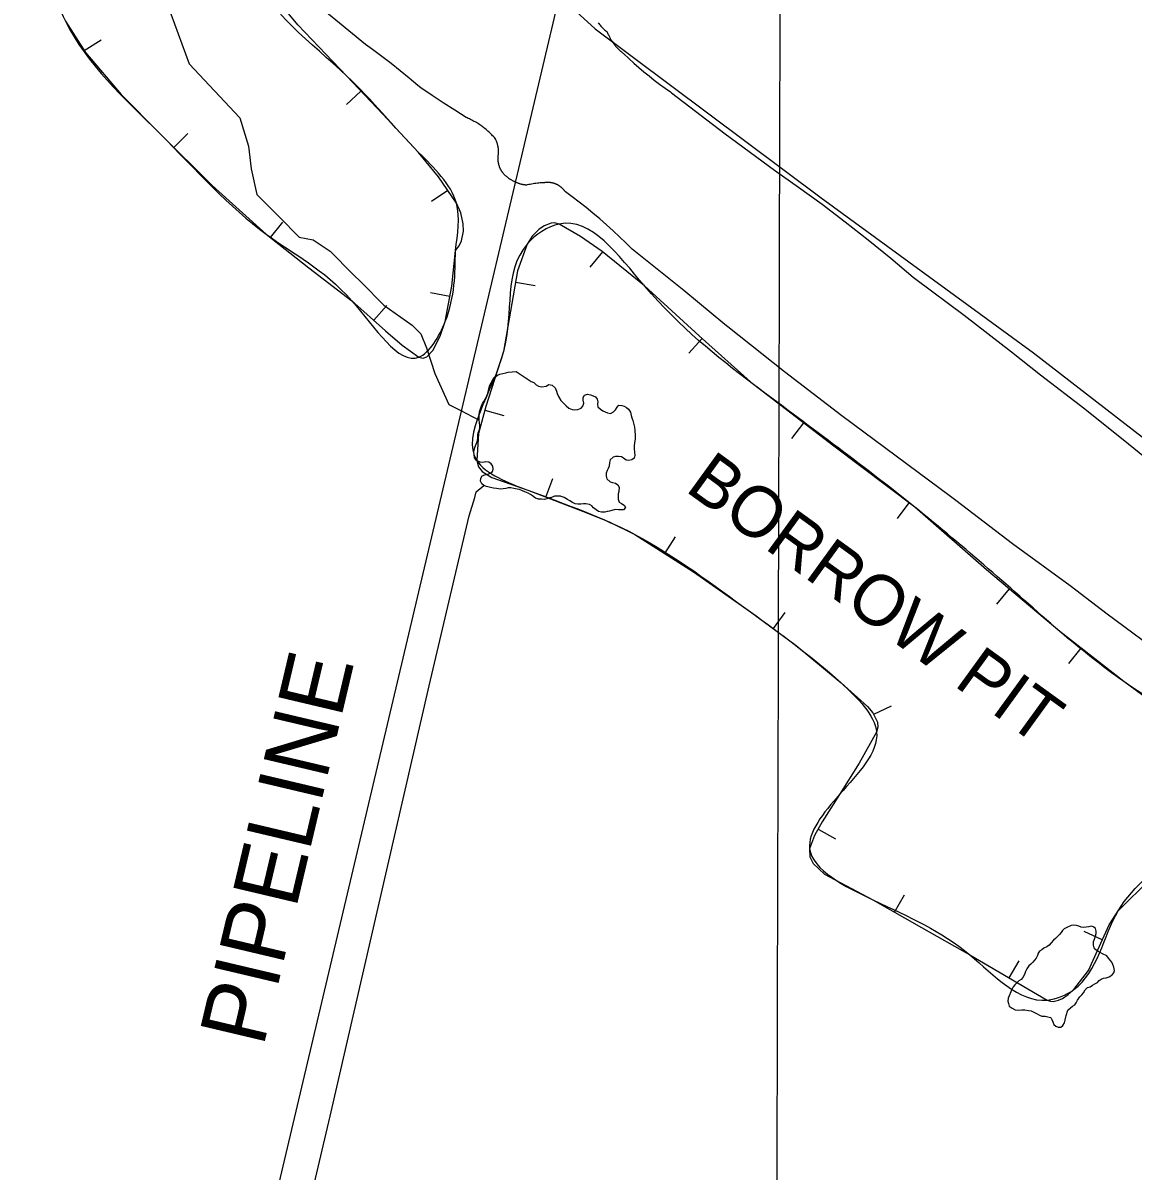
# Model space of a CAD drawing. Extents: x 3172297 to 3210190, y 958463 to 983887.
# Drawn here: x 3186026 to 3187425, y 966663 to 968110 of the extents above; entities that cross this region are included whole.
import ezdxf

# ---------------------------------------------------------------- set-up
doc = ezdxf.new("R2010")
doc.units = 0
for name, color, linetype in [('V-BORW-LINE', 7, 'Continuous'), ('V-GRID-MAJR', 7, 'Continuous'), ('V-LEVE-TOET', 7, 'Continuous'), ('V-RIVR-RANG', 7, 'Continuous'), ('V-TOPO-SHOR', 7, 'Continuous'), ('V-UTIL-IDEN', 7, 'Continuous'), ('V-UTIL-LINE', 7, 'Continuous')]:
    doc.layers.add(name, color=color, linetype=linetype)

msp = doc.modelspace()

# ---------------------------------------------------------------- linework, layer by layer
at = {"layer": 'V-BORW-LINE'}
for p, q in [((3186103.2, 968075), (3186124.3, 968088.5)), ((3186451.8, 968024.1), (3186433.6, 968007)), ((3186216.2, 967952.8), (3186233.8, 967970.5)), ((3186561.3, 967898.9), (3186540.6, 967884.8)), ((3186338, 967839.3), (3186353.5, 967858.9)), ((3186756.2, 967821.6), (3186740.5, 967802.2)), ((3186646.6, 967783.3), (3186671.3, 967779.1)), ((3186564, 967765), (3186539.5, 967769.6)), ((3186468, 967735.2), (3186484.6, 967753.9)), ((3186881.9, 967712.3), (3186865.2, 967693.6)), ((3186608, 967621.7), (3186632.1, 967615.1)), ((3187009.8, 967605.8), (3186994.6, 967586)), ((3186684.7, 967512.3), (3186693.7, 967535.7)), ((3187142.6, 967505.1), (3187127.6, 967485.2)), ((3186834.8, 967441.3), (3186848.2, 967462.4)), ((3187269, 967396.6), (3187252.9, 967377.5)), ((3186971.7, 967346.5), (3186986.5, 967366.7)), ((3187359, 967322.1), (3187343.6, 967302.5)), ((3187098.1, 967238.6), (3187120.6, 967249.4)), ((3187028, 967093.8), (3187049.8, 967081.5)), ((3187124.5, 966989.2), (3187136.8, 967011)), ((3187386.2, 966954.5), (3187363.4, 966964.7)), ((3187268.9, 966906.3), (3187281.5, 966927.9))]:
    msp.add_line(p, q, dxfattribs=at)
for points in [[(3186570.9, 967823), (3186575.6, 967829.1), (3186578.5, 967835.3), (3186581, 967847.3), (3186580.8, 967856.8), (3186577.8, 967870.7), (3186572.1, 967882.8), (3186549.8, 967915.8), (3186524.6, 967946.8), (3186479.3, 967994.9), (3186434, 968043), (3186372.5, 968107.6), (3186313.9, 968178.4)], [(3186079.4, 968112.2), (3186104.8, 968072.6), (3186149.7, 968019.6), (3186198.8, 967970), (3186264.2, 967905.1), (3186332.5, 967843.6), (3186386.3, 967801.4), (3186440.4, 967759.7), (3186483, 967721.9)], [(3187332.6, 967342.9), (3187240.5, 967420.7), (3187150, 967499.6), (3187047.9, 967576.4), (3186946.6, 967654.4), (3186878.1, 967715.6), (3186809.3, 967778.5), (3186756, 967821.8), (3186728.7, 967840.8), (3186701.6, 967856.5), (3186696.4, 967857.9), (3186691.6, 967857.6), (3186682.7, 967854.1), (3186676.2, 967849.7), (3186667.6, 967841), (3186661.3, 967831.1), (3186649, 967797.3), (3186631.5, 967695.8), (3186609.4, 967626.7), (3186600.1, 967592.4), (3186597.8, 967558.5), (3186600.2, 967550.4), (3186604.8, 967544.6), (3186616.9, 967536.9), (3186663.3, 967520.6), (3186731.1, 967494.4), (3186764.7, 967481.2), (3186797.1, 967465.2), (3186871.1, 967418.3), (3186942.7, 967367.7), (3187000.5, 967325.4), (3187057, 967278.2), (3187090.5, 967248.5), (3187097.1, 967240.6), (3187102.9, 967228.5), (3187103.3, 967222.4), (3187101.7, 967216.2), (3187079.7, 967176.9), (3187055, 967137.4), (3187033.3, 967103.2), (3187023.7, 967086), (3187017.4, 967069.2), (3187017.6, 967058.8), (3187021.9, 967050.4), (3187036.3, 967037.2), (3187097, 967004.8), (3187158.3, 966969.9), (3187219.5, 966935.2), (3187268.2, 966906.7), (3187316.9, 966878.4), (3187320.9, 966876.9), (3187324.5, 966876.7), (3187331.1, 966878.1), (3187336.1, 966880.5), (3187343.4, 966885.5), (3187350.2, 966891.5), (3187368.8, 966915.7), (3187386.3, 966954.6), (3187394.9, 966973.4), (3187406.1, 966990.7), (3187446.9, 967031.3)], [(3186483, 967721.9), (3186504, 967703.6), (3186525, 967688.7), (3186530.3, 967687.5), (3186534.8, 967689.2), (3186542.3, 967697), (3186551.9, 967715.2), (3186558.2, 967733.8), (3186566.5, 967778.3), (3186570.9, 967823)], [(3187457.9, 967247.2), (3187413.5, 967279.7), (3187373, 967311.2), (3187332.6, 967342.9)]]:
    msp.add_lwpolyline(points, dxfattribs=at)
for points in [[(3186570.9, 967823), (3186558.2, 967733.8), (3186525, 967688.7), (3186440.4, 967759.7), (3186332.5, 967843.6), (3186198.8, 967970), (3186079.4, 968112.2), (3186046.2, 968212.5), (3186028.1, 968294.9), (3186058.5, 968423.3), (3186144.3, 968634.5), (3186233.5, 968911.2), (3186317.2, 969158.1), (3186384.1, 969385.4), (3186404.4, 969615.9), (3186453, 969857.5), (3186463.9, 970055.1), (3186468.3, 970206), (3186442.7, 970412), (3186424.7, 970627), (3186444.1, 970707.7), (3186526.6, 970731.5), (3186576.5, 970720.7), (3186595.8, 970686.3), (3186618.9, 970575.1), (3186622.1, 970412), (3186626.9, 970258.7), (3186635, 970085.5), (3186634.7, 969845.8), (3186644.2, 969674.8), (3186610.1, 969512.4), (3186553.6, 969289.4), (3186481.5, 969027.9), (3186445.6, 968873.5), (3186394.3, 968683.3), (3186345.5, 968468), (3186307, 968292), (3186313.9, 968178.4), (3186434, 968043), (3186524.6, 967946.8), (3186572.1, 967882.8), (3186570.9, 967823)], [(3187332.6, 967342.9), (3187413.5, 967279.7), (3187502.6, 967213), (3187533, 967163.3), (3187488.5, 967075), (3187406.1, 966990.7), (3187350.2, 966891.5), (3187316.9, 966878.4), (3187219.5, 966935.2), (3187097, 967004.8), (3187017.4, 967069.2), (3187055, 967137.4), (3187101.7, 967216.2), (3187057, 967278.2), (3186942.7, 967367.7), (3186797.1, 967465.2), (3186663.3, 967520.6), (3186597.8, 967558.5), (3186631.5, 967695.8), (3186661.3, 967831.1), (3186701.6, 967856.5), (3186809.3, 967778.5), (3186946.6, 967654.4), (3187150, 967499.6), (3187332.6, 967342.9)]]:
    msp.add_spline(points, degree=3, dxfattribs=at)
at = {"layer": 'V-GRID-MAJR'}
msp.add_spline([(3186968.9, 963893.7), (3186984.8, 969954), (3187000.7, 976017.3), (3187016.6, 982080.8), (3187016.6, 982083.8)], degree=3, dxfattribs=at)
at = {"layer": 'V-LEVE-TOET'}
for points in [[(3186621.8, 967962.7), (3186621.6, 967963.2), (3186621.3, 967963.8), (3186621.1, 967964.1), (3186621.1, 967964.1), (3186620, 967965.4), (3186619, 967966.6), (3186617.8, 967967.8), (3186616.7, 967969), (3186615.5, 967970.2), (3186614.4, 967971.3), (3186613.2, 967972.5), (3186612, 967973.6), (3186610.7, 967974.7), (3186609.5, 967975.7), (3186608.2, 967976.8), (3186606.9, 967977.8), (3186605.6, 967978.8), (3186604.3, 967979.8), (3186602.9, 967980.7), (3186601.6, 967981.7), (3186600.2, 967982.6), (3186598.8, 967983.4), (3186597.4, 967984.3), (3186596, 967985.1), (3186594.5, 967985.9), (3186593.1, 967986.7), (3186591.6, 967987.5), (3186590.1, 967988.2), (3186588.6, 967988.9), (3186587.1, 967989.6), (3186585.6, 967990.3), (3186584.6, 967990.7), (3186584.6, 967990.7), (3186570.1, 967999.8), (3186555.7, 968009.1), (3186541.5, 968018.6), (3186527.4, 968028.3), (3186523.7, 968030.9), (3186523.7, 968030.9), (3186512.6, 968040.4), (3186501.3, 968049.7), (3186489.9, 968058.8), (3186478.3, 968067.7), (3186466.6, 968076.4), (3186457.8, 968082.7), (3186457.8, 968082.7), (3186382.7, 968144.6)], [(3186750.9, 968110.1), (3186751.7, 968109.1), (3186752.6, 968108), (3186753.4, 968107), (3186754.3, 968106), (3186755.2, 968105.1), (3186756.1, 968104.1), (3186757.1, 968103.1), (3186758, 968102.2), (3186759, 968101.3), (3186760, 968100.4), (3186761, 968099.5), (3186762, 968098.7), (3186762.4, 968098.3), (3186762.4, 968098.3), (3186762.8, 968097.3), (3186763.2, 968096.3), (3186763.6, 968095.3), (3186764.1, 968094.3), (3186764.6, 968093.4), (3186765.1, 968092.4), (3186765.6, 968091.4), (3186766.1, 968090.5), (3186766.6, 968089.6), (3186767.2, 968088.6), (3186767.8, 968087.7), (3186768.4, 968086.8), (3186769, 968085.9), (3186769.6, 968085), (3186770.2, 968084.1), (3186770.9, 968083.2), (3186771.5, 968082.4), (3186772.2, 968081.5), (3186772.9, 968080.7), (3186773.6, 968079.9), (3186774.3, 968079.1), (3186775.1, 968078.3), (3186775.8, 968077.5)], [(3186775.8, 968077.5), (3186776.6, 968076.7), (3186777.4, 968076), (3186778.2, 968075.2), (3186779, 968074.5), (3186779.8, 968073.8), (3186780.6, 968073.1), (3186781.5, 968072.4), (3186782.3, 968071.7), (3186783.2, 968071.1), (3186783.4, 968070.9), (3186783.4, 968070.9), (3186789.5, 968065.1), (3186795.8, 968059.4), (3186802.1, 968053.9), (3186808.5, 968048.4), (3186815, 968043.1), (3186821.6, 968037.8), (3186828.3, 968032.7), (3186835.1, 968027.7), (3186841.9, 968022.9), (3186843.3, 968021.9), (3186843.3, 968021.9), (3186910.9, 967970.2), (3186973.2, 967924.2), (3186973.2, 967924.2), (3187003.3, 967903.1), (3187033, 967881.4), (3187062.3, 967859.2), (3187091.2, 967836.6), (3187119.7, 967813.4), (3187147.8, 967789.7), (3187151.2, 967786.8), (3187151.2, 967786.8), (3187212, 967741.6), (3187272, 967695.3), (3187308.2, 967666.5), (3187308.2, 967666.5), (3187364.2, 967623.5), (3187419.3, 967579.6), (3187461.5, 967545.1)], [(3186641.3, 967912), (3186640.6, 967912.4), (3186640, 967912.8), (3186639.4, 967913.2), (3186638.8, 967913.6), (3186638.2, 967914), (3186637.6, 967914.5), (3186637, 967914.9), (3186636.4, 967915.4), (3186635.8, 967915.9), (3186635.2, 967916.3), (3186634.7, 967916.8), (3186634.1, 967917.3), (3186633.6, 967917.8), (3186633, 967918.4), (3186632.5, 967918.9), (3186632, 967919.4), (3186631.5, 967920), (3186631, 967920.5), (3186630.7, 967920.9), (3186630.7, 967920.9), (3186630.4, 967921.3), (3186630.1, 967921.8), (3186629.8, 967922.2), (3186629.5, 967922.7), (3186629.2, 967923.1), (3186628.9, 967923.6), (3186628.7, 967924), (3186628.4, 967924.5), (3186628.2, 967925), (3186627.9, 967925.4), (3186627.7, 967925.9), (3186627.5, 967926.4), (3186627.3, 967926.9), (3186627, 967927.4), (3186626.8, 967927.9), (3186626.7, 967928.3), (3186626.5, 967928.8), (3186626.3, 967929.3), (3186626.1, 967929.8), (3186626, 967930.3), (3186625.8, 967930.9), (3186625.7, 967931.4), (3186625.6, 967931.9), (3186625.5, 967932.4), (3186625.3, 967932.9), (3186625.2, 967933.4), (3186625.1, 967933.9), (3186625.1, 967934.5), (3186625, 967935), (3186624.9, 967935.5), (3186624.9, 967936), (3186624.8, 967936.6), (3186624.8, 967937.1), (3186624.8, 967937.6), (3186624.7, 967938.1), (3186624.7, 967938.7), (3186624.7, 967939.2), (3186624.7, 967939.7), (3186624.7, 967940.2), (3186624.8, 967940.8), (3186624.8, 967941.3), (3186624.9, 967941.8), (3186624.9, 967942.3), (3186625, 967942.8), (3186625, 967943.4), (3186625.1, 967943.9), (3186625.2, 967944.4), (3186625.3, 967944.8), (3186625.3, 967944.8), (3186625.3, 967945.4), (3186625.4, 967946), (3186625.4, 967946.6), (3186625.4, 967947.2), (3186625.4, 967947.8), (3186625.4, 967948.4), (3186625.3, 967949), (3186625.3, 967949.5), (3186625.2, 967950.1), (3186625.2, 967950.7), (3186625.1, 967951.3), (3186625.1, 967951.9), (3186625, 967952.5), (3186624.9, 967953.1), (3186624.8, 967953.7), (3186624.7, 967954.3), (3186624.5, 967954.8), (3186624.4, 967955.4), (3186624.3, 967956), (3186624.1, 967956.6), (3186623.9, 967957.1), (3186623.8, 967957.7), (3186623.6, 967958.3), (3186623.4, 967958.8), (3186623.2, 967959.4), (3186623, 967960), (3186622.8, 967960.5), (3186622.6, 967961.1), (3186622.3, 967961.6), (3186622.1, 967962.2), (3186621.8, 967962.7)], [(3186705.6, 967901.6), (3186705.2, 967901.9), (3186704.9, 967902.2), (3186704.5, 967902.5), (3186704.2, 967902.8), (3186703.8, 967903.1), (3186703.4, 967903.4), (3186703, 967903.7), (3186702.7, 967904), (3186702.3, 967904.2), (3186701.9, 967904.5), (3186701.5, 967904.7), (3186701.1, 967905), (3186700.7, 967905.2), (3186700.3, 967905.5), (3186699.9, 967905.7), (3186699.5, 967905.9), (3186699.1, 967906.1), (3186698.6, 967906.3), (3186698.2, 967906.5), (3186697.8, 967906.7), (3186697.4, 967906.9), (3186696.9, 967907), (3186696.5, 967907.2), (3186696.1, 967907.4), (3186695.6, 967907.5), (3186695.2, 967907.7), (3186694.7, 967907.8), (3186694.3, 967907.9), (3186693.8, 967908.1), (3186693.4, 967908.2), (3186692.9, 967908.3), (3186692.5, 967908.4), (3186692, 967908.5), (3186691.6, 967908.5), (3186691.1, 967908.6), (3186690.6, 967908.7), (3186690.2, 967908.7), (3186689.7, 967908.8), (3186689.3, 967908.8), (3186688.8, 967908.8), (3186688.3, 967908.9), (3186687.9, 967908.9), (3186687.4, 967908.9), (3186686.9, 967908.9), (3186686.5, 967908.9), (3186686, 967908.9), (3186685.6, 967908.9), (3186685.1, 967908.8), (3186684.6, 967908.8), (3186684.2, 967908.7), (3186683.7, 967908.7), (3186683.3, 967908.6), (3186683.3, 967908.6), (3186681.5, 967908.5), (3186679.6, 967908.4), (3186677.8, 967908.3), (3186676, 967908.1), (3186674.2, 967907.9), (3186672.4, 967907.7), (3186670.6, 967907.4), (3186668.8, 967907.2), (3186667, 967906.8), (3186665.1, 967906.5), (3186663.3, 967906.1), (3186661.5, 967905.7), (3186660.6, 967905.5), (3186660.6, 967905.5), (3186660, 967905.6), (3186659.4, 967905.6), (3186658.8, 967905.7), (3186658.2, 967905.8), (3186657.6, 967905.8), (3186657, 967905.9), (3186656.4, 967906), (3186655.8, 967906.2), (3186655.2, 967906.3), (3186654.6, 967906.4), (3186654, 967906.6), (3186653.4, 967906.7), (3186652.8, 967906.9), (3186652.2, 967907.1), (3186651.7, 967907.3), (3186651.1, 967907.5), (3186650.5, 967907.7), (3186649.9, 967907.9), (3186649.4, 967908.1), (3186648.8, 967908.3), (3186648.2, 967908.6), (3186647.7, 967908.8), (3186647.3, 967909), (3186647.3, 967909), (3186646.6, 967909.3), (3186645.9, 967909.6), (3186645.2, 967909.9), (3186644.6, 967910.2), (3186643.9, 967910.6), (3186643.2, 967910.9), (3186642.6, 967911.2), (3186641.9, 967911.6), (3186641.3, 967912)], [(3187468.3, 967308.6), (3187392.2, 967364.9), (3187345.8, 967400.3), (3187345.8, 967400.3), (3187273.2, 967453.5), (3187201.6, 967508), (3187195, 967513.1), (3187195, 967513.1), (3187058, 967614.7), (3187058, 967614.7), (3186985.6, 967670.2), (3186914.1, 967726.9), (3186910.4, 967729.9), (3186910.4, 967729.9), (3186858.7, 967772.8), (3186806.4, 967814.7), (3186793.6, 967824.7), (3186793.6, 967824.7), (3186785.8, 967832.7), (3186777.7, 967840.4), (3186769.6, 967848.1), (3186761.3, 967855.6), (3186752.9, 967862.9), (3186744.3, 967870.1), (3186735.7, 967877.2), (3186726.9, 967884.1), (3186718, 967890.8), (3186709.5, 967897), (3186709.5, 967897), (3186709.2, 967897.4), (3186709, 967897.8), (3186708.7, 967898.2), (3186708.4, 967898.5), (3186708.1, 967898.9), (3186707.8, 967899.2), (3186707.5, 967899.6), (3186707.2, 967900), (3186706.9, 967900.3), (3186706.6, 967900.6), (3186706.2, 967901), (3186705.9, 967901.3), (3186705.6, 967901.6)]]:
    msp.add_lwpolyline(points, dxfattribs=at)
at = {"layer": 'V-TOPO-SHOR'}
for points in [[(3186924.2, 969734), (3186888, 969546.6), (3186819.5, 969291.4), (3186695, 968763.2), (3186594, 968374.2), (3186583.2, 968326.1), (3186581.4, 968302.9), (3186588.4, 968277.8), (3186599.1, 968254.6), (3186620.4, 968217.1), (3186700.6, 968145.4), (3186746.9, 968102.5), (3187032.1, 967889.3), (3187299.4, 967694), (3187871.5, 967251.6), (3187882.2, 967233.7), (3187869.6, 967214.1), (3187830.2, 967174.9)], [(3186198.3, 968159.8), (3186235.3, 968058.2), (3186299.4, 967990.2), (3186310, 967954.5), (3186313.5, 967925.9), (3186320.6, 967893.7), (3186349.1, 967865.1), (3186374, 967840), (3186391.8, 967836.4), (3186413.2, 967822.1), (3186441.7, 967793.4), (3186452.4, 967782.7), (3186480.9, 967754.1), (3186516.6, 967729), (3186527.3, 967718.2), (3186534.3, 967700.4), (3186545, 967668.2), (3186562.7, 967628.9), (3186577, 967621.7), (3186600.8, 967609.4)], [(3186627.1, 967667.3), (3186630.7, 967667.9), (3186634.4, 967668.9), (3186637.4, 967669.9), (3186647.7, 967670.6)], [(3186647.7, 967670.6), (3186666.4, 967658.1), (3186669.7, 967656.6), (3186672.8, 967654), (3186675.7, 967652.3), (3186679.7, 967651.2), (3186685.3, 967652.2), (3186688.5, 967654.3), (3186692.9, 967653.2), (3186696.6, 967650.2), (3186698.2, 967646), (3186699.3, 967643), (3186700.7, 967639.1), (3186703.8, 967634.2), (3186706.9, 967631), (3186710.4, 967627.2), (3186713.9, 967624.3), (3186717.9, 967622.8), (3186721, 967622.3), (3186725.4, 967622.7), (3186729.6, 967624.3), (3186731.7, 967627), (3186732.6, 967630.7), (3186732, 967634.5), (3186732, 967637.7), (3186733.8, 967640.6), (3186737.5, 967642), (3186741.1, 967641.3), (3186744.6, 967640), (3186747.5, 967638.5), (3186749.8, 967635.8), (3186750.6, 967632.4), (3186750.2, 967629.3), (3186750.5, 967626.2), (3186753.6, 967623.2), (3186756.8, 967621.1), (3186759.5, 967619.6), (3186762.6, 967618.5), (3186766.6, 967617.6), (3186770.3, 967619.9), (3186772.9, 967622.3), (3186774.6, 967625.7), (3186777.1, 967628.2), (3186780.7, 967627.7), (3186783.8, 967626.8), (3186786.7, 967625.1), (3186789, 967623), (3186791.5, 967619.2), (3186792.5, 967615.2), (3186793.1, 967612.1), (3186794.7, 967608.7), (3186796.7, 967600.3), (3186797.1, 967596.1), (3186797.6, 967589.8), (3186797.4, 967585.2), (3186796.7, 967580.9), (3186796.2, 967576.9), (3186796.4, 967573.1), (3186796.8, 967569.1), (3186796.9, 967564.7), (3186796.1, 967561.4), (3186793.3, 967559.3), (3186789.5, 967558.6), (3186786.2, 967558.8), (3186782.7, 967561.4), (3186780.2, 967563.1), (3186776.6, 967563.5), (3186772.6, 967563.6), (3186769.7, 967562.5), (3186766.1, 967559.2), (3186765.2, 967556.1), (3186764.6, 967551.3), (3186763.5, 967548.4), (3186762, 967545.7), (3186761.1, 967542.3), (3186760.9, 967538.8), (3186761.7, 967535.2), (3186766, 967531.6), (3186769.1, 967530.5), (3186772.9, 967529.9), (3186775.6, 967527.7), (3186777.2, 967525), (3186777, 967519.4), (3186775.9, 967516.4), (3186775.9, 967513.1), (3186776.2, 967509.7), (3186777.4, 967506), (3186780.4, 967504.3), (3186783.5, 967502.1), (3186785.3, 967499), (3186782.8, 967496.3)], [(3186782.8, 967496.3), (3186779.6, 967496.1), (3186776.5, 967496.1), (3186772.1, 967496.6), (3186768.1, 967495.6), (3186765.2, 967494.6), (3186762, 967494.2), (3186759.1, 967493.2), (3186755.1, 967493.2), (3186751.2, 967494.3), (3186748.3, 967496.3), (3186744.9, 967498.8), (3186742.7, 967501.1), (3186740, 967502.8), (3186735.4, 967503.7), (3186732.2, 967503.8), (3186728.9, 967503.4), (3186725.3, 967503.2), (3186721.8, 967503.7), (3186718.6, 967505.4), (3186715.3, 967507.5), (3186712.2, 967509.2), (3186707.8, 967511.6), (3186704.1, 967513.1), (3186703.3, 967513.5), (3186699.1, 967513.5), (3186695.7, 967513.4), (3186691.3, 967511.5), (3186690, 967511.3), (3186686.3, 967510.1), (3186683.3, 967509.3), (3186679.4, 967509.8), (3186675.2, 967509.8), (3186674.8, 967510.3), (3186671.8, 967511.1), (3186667.9, 967513.7), (3186665.4, 967515.6), (3186662.5, 967517.1), (3186658.3, 967519), (3186655.4, 967520.3), (3186651.9, 967522), (3186648.7, 967522.5), (3186644.6, 967523.1), (3186640.8, 967523.8), (3186637.5, 967524.1), (3186634.3, 967523.3), (3186631.2, 967522.7), (3186627.8, 967522.3), (3186622.8, 967523.2), (3186619, 967523.4), (3186615.1, 967524.3), (3186610.3, 967525.6), (3186606.7, 967526.9), (3186604.3, 967529.2), (3186602.6, 967532.2), (3186602.9, 967536.2), (3186604.6, 967539.1), (3186608.1, 967540.5), (3186611.7, 967541.3), (3186614.7, 967542.5), (3186617.6, 967544.6), (3186618.7, 967547.7), (3186618.1, 967551.3), (3186615.8, 967554.4), (3186613.1, 967556.3), (3186609.4, 967556.8), (3186605.2, 967556), (3186602.1, 967556.5), (3186597.5, 967558.6), (3186595, 967562), (3186594.6, 967566.2), (3186594.2, 967569.3), (3186595.4, 967575), (3186597.1, 967579.1), (3186598.4, 967582), (3186599, 967586.2), (3186599.3, 967590.2), (3186599.5, 967593.3), (3186601, 967596.4), (3186601.9, 967599.4), (3186601.7, 967602.7), (3186601.3, 967605.9), (3186600.8, 967609.4), (3186600.8, 967612.6), (3186600.8, 967615.9), (3186601.5, 967619.7), (3186602.6, 967623.4), (3186603.7, 967627.2), (3186605, 967630.1), (3186606.7, 967632.8), (3186608.8, 967636.7), (3186610.5, 967639.9), (3186611.8, 967642.8), (3186612.7, 967646.7), (3186613.6, 967650.3), (3186614.4, 967653.4), (3186615.9, 967656.5), (3186618, 967660.7), (3186620.8, 967663.6), (3186624, 967665.8), (3186627.1, 967667.3)], [(3186521.2, 965651.5), (3186498.2, 965701.6), (3186412.7, 965782.1), (3186337.8, 965851.9), (3186277.3, 965914.6), (3186252.3, 965937.8), (3186234.5, 965954), (3186229.2, 965961.1), (3186227.4, 965964.7), (3186229.2, 965977.2), (3186247.3, 966061.1), (3186308.6, 966287.7), (3186413.2, 966732), (3186537.8, 967274.5), (3186588.3, 967488.6), (3186595.5, 967511.8), (3186597.3, 967519), (3186606.7, 967526.9)], [(3187372.3, 966971.6), (3187372.2, 966971.7), (3187369.2, 966970.5), (3187365.9, 966970.1), (3187362.8, 966969.9), (3187359.6, 966970.4), (3187356.7, 966971.6), (3187353.6, 966972.3), (3187350.4, 966972.8), (3187346.9, 966972.2), (3187341.4, 966969.7), (3187338.3, 966968.3), (3187335.9, 966966), (3187334.2, 966963.5), (3187332.1, 966961), (3187329.8, 966958.5), (3187327.2, 966956.1), (3187324.9, 966953.8), (3187321.9, 966950.5), (3187319.4, 966947.6), (3187316.2, 966945.3), (3187312.5, 966943.7), (3187309.9, 966941.8), (3187307.2, 966940.2), (3187305.5, 966937.7), (3187304.4, 966934.4), (3187302.9, 966931.2), (3187300.8, 966928.5), (3187298.9, 966926), (3187296.3, 966923.6), (3187293.6, 966921.5), (3187291, 966917.8), (3187289.5, 966914.4), (3187288.2, 966910.5), (3187286.1, 966906.9), (3187284, 966904.5), (3187281.2, 966902.6), (3187278.5, 966900.3), (3187276.2, 966897.6), (3187273.8, 966895.2), (3187272.1, 966891.6), (3187270.8, 966888.7), (3187268.7, 966883.7), (3187267.6, 966880.6), (3187267.1, 966877), (3187267.9, 966873.9), (3187269, 966870.9), (3187272.5, 966868.2), (3187276.6, 966866.2), (3187280.4, 966865.6), (3187284.8, 966865.9), (3187288.6, 966866.1), (3187293.4, 966865.4), (3187296.7, 966864.8), (3187300.7, 966862.6), (3187304.2, 966860.9), (3187307.1, 966859.4), (3187310, 966858.3), (3187314.4, 966857.9), (3187317.6, 966857.4), (3187320.9, 966856.5), (3187321.9, 966855.7), (3187322.7, 966853.8), (3187323.8, 966850.9), (3187325.2, 966847.7), (3187327.7, 966845.6), (3187330.8, 966844.1), (3187333.9, 966844.3), (3187336.5, 966846.3), (3187338.6, 966849.7), (3187339.5, 966853), (3187339.7, 966856.1), (3187340.1, 966857), (3187340.8, 966859), (3187343, 966865.7)], [(3187343, 966865.7), (3187346.1, 966868.6), (3187348.7, 966870.7), (3187351.8, 966872.3), (3187353.5, 966874.8), (3187355.2, 966878.1), (3187358, 966882.3), (3187358.4, 966882.7), (3187360.3, 966884.8), (3187362.5, 966887.7), (3187364.6, 966891.2), (3187367.6, 966894.3), (3187371.1, 966895.1), (3187373.9, 966897), (3187377, 966899), (3187380.2, 966900.4), (3187382.5, 966902.9), (3187385, 966904.6), (3187387.8, 966906), (3187391.3, 966906.4), (3187394.7, 966907.8), (3187398.7, 966910.1), (3187400.6, 966912.6), (3187401.7, 966915.7), (3187400.7, 966919.7), (3187399.5, 966923.2), (3187398.2, 966926.2), (3187396.2, 966928.5), (3187394.1, 966931.3), (3187391.9, 966934.2), (3187386.4, 966936.6), (3187383.7, 966938.3), (3187380.8, 966940), (3187377.9, 966941.9), (3187375.9, 966944.4), (3187375.3, 966947.6), (3187375.3, 966952.2), (3187376.4, 966955.3), (3187377.7, 966959.3), (3187378.6, 966962.2), (3187378.6, 966965.3), (3187377.6, 966968.7), (3187375.7, 966970.4), (3187375.1, 966970.8), (3187372.3, 966971.6)]]:
    msp.add_lwpolyline(points, dxfattribs=at)
at = {"layer": 'V-UTIL-LINE'}
msp.add_lwpolyline([(3187111.3, 971559.6), (3187055.5, 969641.3), (3186187.8, 965968.4)], dxfattribs=at)

# ---------------------------------------------------------------- texts
at = {"layer": 'V-RIVR-RANG'}
msp.add_text('BORROW PIT', height=64, rotation=324.0685, dxfattribs=at).set_placement((3186858.9, 967521))
at = {"layer": 'V-UTIL-IDEN'}
msp.add_text('PIPELINE', height=83, rotation=76.7071, dxfattribs=at).set_placement((3186328.7, 966817.9))

doc.saveas('drawing.dxf')
